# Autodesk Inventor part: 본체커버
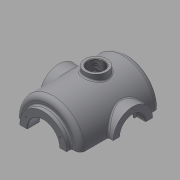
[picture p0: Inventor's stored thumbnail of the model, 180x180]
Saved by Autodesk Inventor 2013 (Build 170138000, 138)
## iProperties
Created: 2016-02
Part Number: 본체커버
Material: 일반
Document SubType Name: Modeling
Designer: mduedu
Density: 2.71 g/cm^3
Author: mduedu
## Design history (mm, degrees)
sketch "스케치2"
  geometry: L1 (0, 90)-(0, -90); L2 (65, -65.993)-(65, 90); L3 (65, 90)-(0, 90); A1 r 100 centre (0, 10) between (0, -90) and (65, -65.993); 2 further points
  constraints: 6 end point, 2 point on circle, 1 centre point, 1 coincident, 1 horizontal, 1 midpoint, 1 parallel, 1 point on line, 1 vertical
  dimensions: "d3" = 180 distance of L1.start L1.end; "d5" = 130 diameter of L2 L1; "d6" = 100 radius of A1
revolve "회전1" sketch "스케치2" stored, may be unused: angle "d7" = 90 deg
sketch "스케치3"
  geometry: C1 r 47.5 at (0, 0); 1 further point
  constraints: 1 centre point, 1 coincident
  dimensions: "d8" = 95 diameter of C1
extrude "돌출2" join sketch "스케치3" distance "d10" = 10; taper "d11" = 0 deg
sketch "스케치5"
  geometry: L1 (47.5, 100)-(47.5, 90) reference; L2 (47.5, 90)-(65, 90) reference; L3 (65, 90)-(65, -65.993) reference; L4 (-65, -65.993)-(-65, 90) reference; L5 (-65, 90)-(-47.5, 90) reference; L6 (-47.5, 90)-(-47.5, 100) reference; L7 (-47.5, 100)-(47.5, 100) reference; L8 (55, 75)-(55, -61.239); L9 (0, 75)-(55, 75); L10 (0, 75)-(0, -80); A1 r 100 centre (0, 10) between (-65, -65.993) and (0, -90) reference; A2 r 100 centre (0, 10) between (0, -90) and (65, -65.993) reference; A3 r 90 centre (0, 10) between (0, -80) and (55, -61.239); 1 further point
  constraints: 6 end point, 2 point on circle, 1 centre point, 1 parallel, 1 perpendicular, 1 point on line, 1 vertical
  dimensions: "d13" = 10 distance between parallel lines of L3 L8; "d14" = 10 radial gap between concentric circles of A3 A1; "d15" = 15 distance between parallel lines of L9 L2
revolve "회전2" sketch "스케치5" stored, may be unused: angle "d16" = 90 deg
hole "구멍1" diameter "d19" = 65; stored, may be unused: countersink angle "d23" = 90 deg, drill point angle "d25" = 118 deg; dims "d17" = 10, "d18" = 10, "d20" = 6, "d21" = 4, "d22" = 2, "d24" = 8
node "작업 평면1"
sketch "스케치6"
  geometry: L1 (47.5, 100)-(-47.5, 100) reference; C1 r 40 at (0, -7); 1 further point
  constraints: 1 centre point, 1 vertical alignment
  dimensions: "d27" = 80 diameter of C1; "d29" = 107 distance from line of C1.centre L1
extrude "돌출3" join sketch "스케치6" stored distance "d30" = 10; taper "d31" = 0 deg
hole "구멍2" diameter "d34" = 42; stored, may be unused: countersink angle "d38" = 90 deg, drill point angle "d40" = 118 deg; dims "d32" = 10, "d33" = 10, "d35" = 6, "d36" = 52, "d37" = 18, "d39" = 8
sketch "스케치7" dims "d41" = 65
  geometry: C1 r 40 at (0, 0) reference; 3 further points
  constraints: 2 vertical alignment, 1 coincident, 2 other
hole "구멍3" sketch "스케치7" at (0, 32.5) diameter "d43" = 3.242; stored, may be unused: countersink angle "d47" = 90 deg, drill point angle "d49" = 118 deg; dims "d44" = 11, "d45" = 13, "d46" = 18, "d48" = 13
sketch "스케치8" dims "d53" = 80
  geometry: 3 further points
  constraints: 2 vertical alignment, 1 coincident, 2 other
hole "구멍4" sketch "스케치8" at (0, -40) diameter "d56" = 3.242; stored, may be unused: countersink angle "d60" = 90 deg, drill point angle "d62" = 118 deg; dims "d57" = 11, "d58" = 13, "d59" = 18, "d61" = 13
fillet "모깎기1" dims "d66" = 10
fillet "모깎기2" dims "d67" = 3
fillet "모깎기3" dims "d68" = 0.3
chamfer "모따기1" distance "d69" = 1; stored, may be unused: second distance "d70" = 2, angle "d71" = 45 deg
node "작업 평면5"
sketch "스케치10"
  geometry: L1 (-50, 66)-(50, 66); L2 (50, 66)-(50, 50); L3 (50, 50)-(-50, 50); L4 (-50, 50)-(-50, 66); 2 further points
  constraints: 8 end point, 2 horizontal, 2 vertical, 1 midpoint, 1 vertical alignment
  dimensions: "d177" = 50 distance from line of L3 point (0, 0); "d178" = 100 distance of L1.start L1.end; "d179" = 16 distance of L3.end L1.start
extrude "돌출5" join sketch "스케치10" stored distance "d84" = 10; taper "d85" = 0 deg
sketch "스케치21" dims "d180" = 220, "d182" = 130
  geometry: L1 (65, 58)-(-65, 58); L2 (-65, 58)-(-65, -32); L3 (-65, -32)-(65, -32); L4 (65, -32)-(65, 58); L5 (50, 50)-(50, 66) reference; 4 further points
  constraints: 8 end point, 3 horizontal alignment, 3 midpoint, 2 parallel, 1 horizontal, 1 perpendicular, 1 vertical alignment, 4 other
extrude "돌출13" join sketch "스케치21" distance "d183" = 10; taper "d184" = 0 deg
sketch "스케치11"
  geometry: L1 (-65, 80)-(-65, -61.239) reference; L2 (-100, -97)-(-100, -32) reference; L3 (-65, -42.793)-(-100, -63); L4 (-100, -97)-(-110, -97) reference; 1 further point
  constraints: 2 end point, 2 point on line
  dimensions: "d185" = 34 distance from line of L3.end L4; "d186" = 120 deg angle of L2 L3
feature "리브1" sketch "스케치11" dims "d88" = 1, "d89" = 16, "d90" = 0, "d91" = 0, "d92" = 1, "d93" = 1
fillet "모깎기12"
fillet "모깎기13"
fillet "모깎기16" dims "d167" = 3
fillet "모깎기18"
fillet "모깎기17" dims "d168" = 3
fillet "모깎기19" dims "d187" = 3
node "작업 평면6"
sketch "스케치19"
  geometry: L1 (75, -47)-(75, 33) reference; L2 (-75, -47)-(-75, 33) reference; L3 (75, -7)-(-75, -7); C1 r 22.5 at (0, -7); 1 further point
  constraints: 3 midpoint, 2 end point, 1 centre point
  dimensions: "d149" = 45 diameter of C1
extrude "돌출11" join sketch "스케치19" stored distance "d150" = 10; taper "d151" = 0 deg
hole "구멍6" diameter "d154" = 33.376; stored, may be unused: countersink angle "d158" = 90 deg, drill point angle "d160" = 118 deg; dims "d155" = 6, "d156" = 4, "d157" = 2, "d159" = 8, "d190" = 10, "d191" = 10
fillet "모깎기11" dims "d161" = 3
chamfer "모따기3" distance "d164" = 1; stored, may be unused: second distance "d165" = 2, angle "d166" = 45 deg
sketch "스케치22" dims "d189" = 20
  geometry: L1 (-10, -123)-(10, -123); L2 (10, -123)-(10, -103); L3 (10, -103)-(-10, -103); L4 (-10, -103)-(-10, -123); A1 r 65 centre (0, -58) between (-65, -58) and (65, -58) reference; 2 further points
  constraints: 8 end point, 2 parallel, 1 horizontal, 1 horizontal alignment, 1 midpoint, 1 perpendicular, 1 tangent, 1 vertical alignment, 2 other
  dimensions: "d193" = 30 dimension on L1
extrude "돌출14" cut sketch "스케치22" stored distance "d194" = 10; taper "d195" = 0 deg
fillet "모깎기21" dims "d196" = 3
feature "분할1"
node "솔리드2"
pattern_circular "원형 패턴1" dims angle "d51" = 360 deg
mirror "대칭1"
pattern_circular "원형 패턴2" dims angle "d64" = 360 deg
node "절단 모서리 투영1"
other parameters: "d26" = 75, "d136" = 175
